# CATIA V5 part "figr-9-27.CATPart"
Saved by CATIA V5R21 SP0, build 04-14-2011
Part number: Part1
Bounding box of the stored display mesh (mm): x -75 to 75, y -50 to 50, z 0 to 40
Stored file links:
  D:\CATIA V5R21 E-RESOURCES\CATIA-V5R21\catia-v5r21-prt\c09-catia-v5r20-prt\c09-catia-v5r21-figr-9-27.CATPart
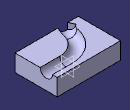
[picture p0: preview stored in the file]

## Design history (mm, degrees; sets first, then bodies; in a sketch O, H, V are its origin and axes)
Body1 (main body)
  Sketch1 on xy-plane, origin (0, 0, 0), H (1, 0, 0), V (0, 1, 0)
    line L1 (-75, 50) -> (75, 50)
    line L2 (75, 50) -> (75, -50)
    line L3 (75, -50) -> (-75, -50)
    line L4 (-75, -50) -> (-75, 50)
    axis line L5 (75, -50) -> (-75, 50)
    length L2 = 100
    length L3 = 150
    horizontal: L1 H, L3 H
    vertical: L2 V, L4 V
    midpoint: O L5
  Pad1: profile Sketch1, direction (0, 0, 1), length 40
  Sketch2 on face of Pad1, origin (75, 0, 0), H (0, 1, 0), V (0, 0, 1)
    arc A1 centre (24.1478, 40) radius 14.6047 from (9.543, 40) to (38.7525, 40) ccw
    point P1 (24.1478, 40)
    reference projected point E1 (24.1478, 40) from vertex of Sketch3
    line L1 (9.543, 40) -> (38.7525, 40)
    coincidence: P1 E1
    horizontal: L1 H
  Sketch3 on face of Pad1, origin (0, 0, 40), H (1, 0, 0), V (0, 1, 0)
    point P1 (75, 24.1478)
    line L1 (75, 24.1478) -> (28.6577, 24.1478)
    arc A1 centre (28.6577, -39.2062) radius 63.354 from (28.6577, 24.1478) to (-33.8383, -28.8149) ccw
    arc A2 centre (-62.192, -24.1005) radius 28.7429 from (-33.8383, -28.8149) to (-49.7271, -50) cw
    point P6 (-49.7271, -50)
    reference projected line E1 (75, -50) -> (75, 50) from edge [face of Pad1 | face of Pad1]
    reference projected line E2 (-75, -50) -> (75, -50) from edge [face of Pad1 | face of Pad1]
    horizontal: L1 H
    tangency: A1 L1, A2 A1
    coincidence: P1 E1, P6 E2
  Slot1: profile Sketch2, centre curve Sketch3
